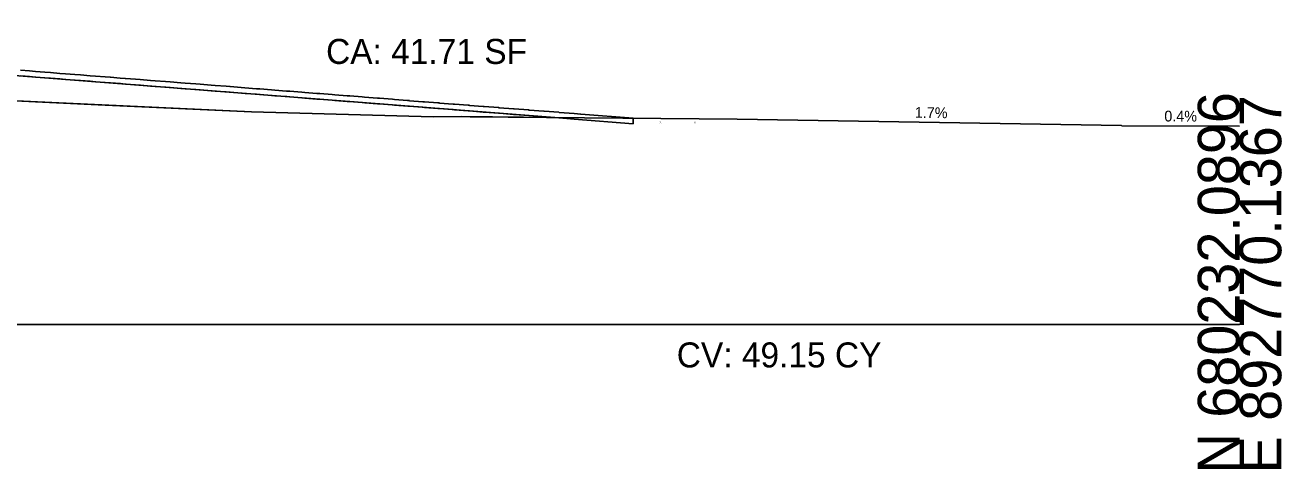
# Model space of a CAD drawing. Extents: x -26 to 4303, y -13 to 10775.
# Drawn here: x 218.5 to 302.8, y 1490.3 to 1520.1 of the extents above; entities that cross this region are included whole.
import ezdxf

# ---------------------------------------------------------------- set-up
doc = ezdxf.new("R2010")
doc.units = 0
for name, color, linetype in [('DTM_P_FINISHED_GRADE', 7, 'Continuous'), ('DTM_X_GROUND', 7, 'Continuous'), ('X_PROFILES_1', 7, 'Continuous'), ('XS_CELL', 7, 'Continuous'), ('XS_M_SHAPES_EARTHWORK', 7, 'Continuous'), ('XS_P_DR_GRAVEL', 7, 'Continuous'), ('XS_P_TX_FS_BS', 7, 'Continuous'), ('XS_SHEET_EW_TX_AREA', 7, 'Continuous'), ('XS_SHEET_EW_TX_VOLUME', 7, 'Continuous')]:
    doc.layers.add(name, color=color, linetype=linetype)

msp = doc.modelspace()

# ---------------------------------------------------------------- linework, layer by layer
at = {"layer": 'DTM_P_FINISHED_GRADE'}
for p, q in [((218.212, 1517.075), (218.812, 1517.028)), ((218.812, 1517.028), (219.21, 1516.997)), ((219.21, 1516.997), (219.216, 1516.997)), ((219.216, 1516.997), (219.826, 1516.949)), ((219.826, 1516.949), (220.214, 1516.919)), ((220.214, 1516.919), (220.22, 1516.918)), ((220.22, 1516.918), (220.841, 1516.869)), ((220.841, 1516.869), (221.218, 1516.84)), ((221.218, 1516.84), (221.223, 1516.84)), ((221.223, 1516.84), (221.856, 1516.79)), ((221.856, 1516.79), (222.221, 1516.762)), ((222.221, 1516.762), (222.227, 1516.761)), ((222.227, 1516.761), (222.871, 1516.711)), ((222.871, 1516.711), (223.225, 1516.683)), ((223.225, 1516.683), (223.231, 1516.683)), ((223.231, 1516.683), (223.885, 1516.631)), ((223.885, 1516.631), (224.229, 1516.605)), ((224.229, 1516.605), (224.234, 1516.604)), ((224.234, 1516.604), (224.9, 1516.552)), ((224.9, 1516.552), (225.233, 1516.526)), ((225.233, 1516.526), (225.238, 1516.526)), ((225.238, 1516.526), (225.915, 1516.473)), ((225.915, 1516.473), (226.237, 1516.448)), ((226.237, 1516.448), (226.242, 1516.447)), ((226.242, 1516.447), (226.93, 1516.393)), ((226.93, 1516.393), (227.24, 1516.369)), ((227.24, 1516.369), (227.245, 1516.369)), ((227.245, 1516.369), (227.944, 1516.314)), ((227.944, 1516.314), (228.244, 1516.291)), ((228.244, 1516.291), (228.249, 1516.29)), ((228.249, 1516.29), (228.959, 1516.235)), ((228.959, 1516.235), (229.248, 1516.212)), ((229.248, 1516.212), (229.252, 1516.212)), ((229.252, 1516.212), (229.974, 1516.155)), ((229.974, 1516.155), (230.252, 1516.134)), ((230.252, 1516.134), (230.256, 1516.133)), ((230.256, 1516.133), (230.989, 1516.076)), ((230.989, 1516.076), (231.256, 1516.055)), ((231.256, 1516.055), (231.26, 1516.055)), ((231.26, 1516.055), (232.003, 1515.997)), ((232.003, 1515.997), (232.26, 1515.977)), ((232.26, 1515.977), (232.263, 1515.976)), ((232.263, 1515.976), (233.018, 1515.917)), ((233.018, 1515.917), (233.263, 1515.898)), ((233.263, 1515.898), (233.267, 1515.898)), ((233.267, 1515.898), (234.033, 1515.838)), ((234.033, 1515.838), (234.267, 1515.82)), ((234.267, 1515.82), (234.271, 1515.819)), ((234.271, 1515.819), (235.048, 1515.758)), ((235.048, 1515.758), (235.271, 1515.741)), ((235.271, 1515.741), (235.274, 1515.741)), ((235.274, 1515.741), (236.062, 1515.679)), ((236.062, 1515.679), (236.275, 1515.663)), ((236.275, 1515.663), (236.278, 1515.662)), ((236.278, 1515.662), (237.077, 1515.6)), ((237.077, 1515.6), (237.279, 1515.584)), ((237.279, 1515.584), (237.282, 1515.584)), ((237.282, 1515.584), (238.092, 1515.52)), ((238.092, 1515.52), (238.282, 1515.506)), ((238.282, 1515.506), (238.285, 1515.505)), ((238.285, 1515.505), (239.106, 1515.441)), ((239.106, 1515.441), (239.286, 1515.427)), ((239.286, 1515.427), (239.289, 1515.427)), ((239.289, 1515.427), (240.121, 1515.362)), ((240.121, 1515.362), (240.29, 1515.349)), ((240.29, 1515.349), (240.293, 1515.348)), ((240.293, 1515.348), (241.136, 1515.282)), ((241.136, 1515.282), (241.294, 1515.27)), ((241.294, 1515.27), (241.296, 1515.27)), ((241.296, 1515.27), (242.151, 1515.203)), ((242.151, 1515.203), (242.298, 1515.192)), ((242.298, 1515.192), (242.3, 1515.191)), ((242.3, 1515.191), (243.166, 1515.124)), ((243.166, 1515.124), (243.302, 1515.113)), ((243.302, 1515.113), (243.304, 1515.113)), ((243.304, 1515.113), (244.18, 1515.044)), ((244.18, 1515.044), (244.305, 1515.035)), ((244.305, 1515.035), (244.307, 1515.034)), ((244.307, 1515.034), (245.195, 1514.965)), ((245.195, 1514.965), (245.309, 1514.956)), ((245.309, 1514.956), (245.311, 1514.956)), ((245.311, 1514.956), (246.21, 1514.886)), ((246.21, 1514.886), (246.313, 1514.878)), ((246.313, 1514.878), (246.315, 1514.877)), ((246.315, 1514.877), (247.225, 1514.806)), ((247.225, 1514.806), (247.317, 1514.799)), ((247.317, 1514.799), (247.318, 1514.799)), ((247.318, 1514.799), (248.239, 1514.727)), ((248.239, 1514.727), (248.321, 1514.721)), ((248.321, 1514.721), (248.322, 1514.72)), ((248.322, 1514.72), (249.254, 1514.648)), ((249.254, 1514.648), (249.324, 1514.642)), ((249.324, 1514.642), (249.325, 1514.642)), ((249.325, 1514.642), (250.269, 1514.568)), ((250.269, 1514.568), (250.328, 1514.564)), ((250.328, 1514.564), (250.329, 1514.563)), ((250.329, 1514.563), (251.284, 1514.489)), ((251.284, 1514.489), (251.332, 1514.485)), ((251.332, 1514.485), (251.333, 1514.485)), ((251.333, 1514.485), (252.298, 1514.409)), ((252.298, 1514.409), (252.336, 1514.407)), ((252.336, 1514.407), (252.337, 1514.406)), ((252.337, 1514.406), (253.313, 1514.33)), ((253.313, 1514.33), (253.34, 1514.328)), ((253.34, 1514.328), (253.34, 1514.328)), ((253.34, 1514.328), (254.328, 1514.251)), ((254.328, 1514.251), (254.343, 1514.25)), ((254.343, 1514.25), (254.344, 1514.25)), ((254.344, 1514.25), (255.343, 1514.171)), ((255.343, 1514.171), (255.347, 1514.171)), ((255.347, 1514.171), (255.347, 1514.171)), ((255.347, 1514.171), (255.789, 1514.136))]:
    msp.add_line(p, q, dxfattribs=at)
at = {"layer": 'DTM_X_GROUND'}
msp.add_lwpolyline([(214.069, 1515.192), (233.709, 1514.282), (245.883, 1513.954), (247.772, 1513.966), (248.38, 1513.947), (266.299, 1513.788), (292.07, 1513.357), (292.103, 1513.35), (300, 1513.32)], dxfattribs=at)
at = {"layer": 'XS_CELL'}
msp.add_line((150, 1500), (300, 1500), dxfattribs=at)
at = {"layer": 'XS_P_DR_GRAVEL'}
for p, q in [((218.812, 1517.028), (218.212, 1517.075)), ((219.21, 1516.997), (218.812, 1517.028)), ((218.218, 1516.7), (218.817, 1516.653)), ((218.817, 1516.653), (219.215, 1516.622)), ((219.216, 1516.997), (219.21, 1516.997)), ((219.215, 1516.622), (219.221, 1516.621)), ((219.826, 1516.949), (219.216, 1516.997)), ((219.221, 1516.621), (219.832, 1516.574)), ((220.214, 1516.919), (219.826, 1516.949)), ((219.832, 1516.574), (220.219, 1516.543)), ((220.22, 1516.918), (220.214, 1516.919)), ((220.219, 1516.543), (220.225, 1516.543)), ((220.841, 1516.869), (220.22, 1516.918)), ((220.225, 1516.543), (220.847, 1516.494)), ((221.218, 1516.84), (220.841, 1516.869)), ((220.847, 1516.494), (221.223, 1516.465)), ((221.223, 1516.84), (221.218, 1516.84)), ((221.856, 1516.79), (221.223, 1516.84)), ((221.223, 1516.465), (221.229, 1516.464)), ((221.229, 1516.464), (221.861, 1516.415)), ((222.221, 1516.762), (221.856, 1516.79)), ((221.861, 1516.415), (222.227, 1516.386)), ((222.227, 1516.761), (222.221, 1516.762)), ((222.871, 1516.711), (222.227, 1516.761)), ((222.227, 1516.386), (222.232, 1516.386)), ((222.232, 1516.386), (222.876, 1516.336)), ((223.225, 1516.683), (222.871, 1516.711)), ((222.876, 1516.336), (223.231, 1516.308)), ((223.231, 1516.683), (223.225, 1516.683)), ((223.885, 1516.631), (223.231, 1516.683)), ((223.231, 1516.308), (223.236, 1516.307)), ((223.236, 1516.307), (223.891, 1516.256)), ((224.229, 1516.605), (223.885, 1516.631)), ((223.891, 1516.256), (224.234, 1516.229)), ((224.234, 1516.604), (224.229, 1516.605)), ((224.9, 1516.552), (224.234, 1516.604)), ((224.234, 1516.229), (224.24, 1516.229)), ((224.24, 1516.229), (224.906, 1516.177)), ((225.233, 1516.526), (224.9, 1516.552)), ((224.906, 1516.177), (225.238, 1516.151)), ((225.238, 1516.526), (225.233, 1516.526)), ((225.915, 1516.473), (225.238, 1516.526)), ((226.237, 1516.448), (225.915, 1516.473)), ((226.242, 1516.447), (226.237, 1516.448)), ((226.93, 1516.393), (226.242, 1516.447)), ((227.24, 1516.369), (226.93, 1516.393)), ((227.245, 1516.369), (227.24, 1516.369)), ((227.944, 1516.314), (227.245, 1516.369)), ((228.244, 1516.291), (227.944, 1516.314)), ((228.249, 1516.29), (228.244, 1516.291)), ((228.959, 1516.235), (228.249, 1516.29)), ((229.248, 1516.212), (228.959, 1516.235)), ((229.252, 1516.212), (229.248, 1516.212)), ((229.974, 1516.155), (229.252, 1516.212)), ((225.238, 1516.151), (225.243, 1516.15)), ((225.243, 1516.15), (225.92, 1516.098)), ((225.92, 1516.098), (226.242, 1516.072)), ((226.242, 1516.072), (226.247, 1516.072)), ((226.247, 1516.072), (226.935, 1516.018)), ((226.935, 1516.018), (227.246, 1515.994)), ((227.246, 1515.994), (227.251, 1515.994)), ((227.251, 1515.994), (227.95, 1515.939)), ((227.95, 1515.939), (228.25, 1515.915)), ((228.25, 1515.915), (228.254, 1515.915)), ((228.254, 1515.915), (228.964, 1515.859)), ((228.964, 1515.859), (229.253, 1515.837)), ((229.253, 1515.837), (229.258, 1515.837)), ((229.258, 1515.837), (229.979, 1515.78)), ((230.252, 1516.134), (229.974, 1516.155)), ((229.979, 1515.78), (230.257, 1515.758)), ((230.256, 1516.133), (230.252, 1516.134)), ((230.989, 1516.076), (230.256, 1516.133)), ((230.257, 1515.758), (230.262, 1515.758)), ((230.262, 1515.758), (230.994, 1515.701)), ((231.256, 1516.055), (230.989, 1516.076)), ((230.994, 1515.701), (231.261, 1515.68)), ((231.26, 1516.055), (231.256, 1516.055)), ((232.003, 1515.997), (231.26, 1516.055)), ((231.261, 1515.68), (231.265, 1515.68)), ((231.265, 1515.68), (232.009, 1515.621)), ((232.26, 1515.977), (232.003, 1515.997)), ((232.009, 1515.621), (232.265, 1515.601)), ((232.263, 1515.976), (232.26, 1515.977)), ((233.018, 1515.917), (232.263, 1515.976)), ((232.265, 1515.601), (232.269, 1515.601)), ((232.269, 1515.601), (233.024, 1515.542)), ((233.263, 1515.898), (233.018, 1515.917)), ((233.024, 1515.542), (233.269, 1515.523)), ((233.267, 1515.898), (233.263, 1515.898)), ((234.033, 1515.838), (233.267, 1515.898)), ((233.269, 1515.523), (233.273, 1515.523)), ((233.273, 1515.523), (234.038, 1515.463)), ((234.267, 1515.82), (234.033, 1515.838)), ((234.038, 1515.463), (234.272, 1515.444)), ((234.271, 1515.819), (234.267, 1515.82)), ((235.048, 1515.758), (234.271, 1515.819)), ((234.272, 1515.444), (234.276, 1515.444)), ((234.276, 1515.444), (235.053, 1515.383)), ((235.271, 1515.741), (235.048, 1515.758)), ((235.053, 1515.383), (235.276, 1515.366)), ((235.274, 1515.741), (235.271, 1515.741)), ((236.062, 1515.679), (235.274, 1515.741)), ((235.276, 1515.366), (235.28, 1515.366)), ((235.28, 1515.366), (236.068, 1515.304)), ((236.275, 1515.663), (236.062, 1515.679)), ((236.278, 1515.662), (236.275, 1515.663)), ((237.077, 1515.6), (236.278, 1515.662)), ((237.279, 1515.584), (237.077, 1515.6)), ((237.282, 1515.584), (237.279, 1515.584)), ((238.092, 1515.52), (237.282, 1515.584)), ((238.282, 1515.506), (238.092, 1515.52)), ((238.285, 1515.505), (238.282, 1515.506)), ((239.106, 1515.441), (238.285, 1515.505)), ((239.286, 1515.427), (239.106, 1515.441)), ((239.289, 1515.427), (239.286, 1515.427)), ((240.121, 1515.362), (239.289, 1515.427)), ((240.29, 1515.349), (240.121, 1515.362)), ((240.293, 1515.348), (240.29, 1515.349)), ((241.136, 1515.282), (240.293, 1515.348)), ((236.068, 1515.304), (236.28, 1515.287)), ((236.28, 1515.287), (236.284, 1515.287)), ((236.284, 1515.287), (237.083, 1515.225)), ((237.083, 1515.225), (237.284, 1515.209)), ((237.284, 1515.209), (237.287, 1515.209)), ((237.287, 1515.209), (238.097, 1515.145)), ((238.097, 1515.145), (238.288, 1515.13)), ((238.288, 1515.13), (238.291, 1515.13)), ((238.291, 1515.13), (239.112, 1515.066)), ((239.112, 1515.066), (239.292, 1515.052)), ((239.292, 1515.052), (239.294, 1515.052)), ((239.294, 1515.052), (240.127, 1514.987)), ((240.127, 1514.987), (240.296, 1514.973)), ((240.296, 1514.973), (240.298, 1514.973)), ((240.298, 1514.973), (241.142, 1514.907)), ((241.294, 1515.27), (241.136, 1515.282)), ((241.142, 1514.907), (241.299, 1514.895)), ((241.296, 1515.27), (241.294, 1515.27)), ((242.151, 1515.203), (241.296, 1515.27)), ((241.299, 1514.895), (241.302, 1514.895)), ((241.302, 1514.895), (242.156, 1514.828)), ((242.298, 1515.192), (242.151, 1515.203)), ((242.156, 1514.828), (242.303, 1514.816)), ((242.3, 1515.191), (242.298, 1515.192)), ((243.166, 1515.124), (242.3, 1515.191)), ((242.303, 1514.816), (242.305, 1514.816)), ((242.305, 1514.816), (243.171, 1514.749)), ((243.302, 1515.113), (243.166, 1515.124)), ((243.171, 1514.749), (243.307, 1514.738)), ((243.304, 1515.113), (243.302, 1515.113)), ((244.18, 1515.044), (243.304, 1515.113)), ((243.307, 1514.738), (243.309, 1514.738)), ((243.309, 1514.738), (244.186, 1514.669)), ((244.305, 1515.035), (244.18, 1515.044)), ((244.186, 1514.669), (244.311, 1514.659)), ((244.307, 1515.034), (244.305, 1515.035)), ((245.195, 1514.965), (244.307, 1515.034)), ((244.311, 1514.659), (244.313, 1514.659)), ((244.313, 1514.659), (245.201, 1514.59)), ((245.309, 1514.956), (245.195, 1514.965)), ((245.201, 1514.59), (245.315, 1514.581)), ((245.311, 1514.956), (245.309, 1514.956)), ((246.21, 1514.886), (245.311, 1514.956)), ((245.315, 1514.581), (245.316, 1514.581)), ((245.316, 1514.581), (246.215, 1514.51)), ((246.313, 1514.878), (246.21, 1514.886)), ((246.215, 1514.51), (246.318, 1514.502)), ((246.315, 1514.877), (246.313, 1514.878)), ((247.225, 1514.806), (246.315, 1514.877)), ((246.318, 1514.502), (246.32, 1514.502)), ((246.32, 1514.502), (247.23, 1514.431)), ((247.317, 1514.799), (247.225, 1514.806)), ((247.318, 1514.799), (247.317, 1514.799)), ((248.239, 1514.727), (247.318, 1514.799)), ((248.321, 1514.721), (248.239, 1514.727)), ((248.322, 1514.72), (248.321, 1514.721)), ((249.254, 1514.648), (248.322, 1514.72)), ((249.324, 1514.642), (249.254, 1514.648)), ((249.325, 1514.642), (249.324, 1514.642)), ((250.269, 1514.568), (249.325, 1514.642)), ((250.328, 1514.564), (250.269, 1514.568)), ((250.329, 1514.563), (250.328, 1514.564)), ((251.284, 1514.489), (250.329, 1514.563)), ((251.332, 1514.485), (251.284, 1514.489)), ((251.333, 1514.485), (251.332, 1514.485)), ((252.298, 1514.409), (251.333, 1514.485)), ((247.23, 1514.431), (247.322, 1514.424)), ((247.322, 1514.424), (247.324, 1514.424)), ((247.324, 1514.424), (248.245, 1514.352)), ((248.245, 1514.352), (248.326, 1514.345)), ((248.326, 1514.345), (248.327, 1514.345)), ((248.327, 1514.345), (249.259, 1514.272)), ((249.259, 1514.272), (249.33, 1514.267)), ((249.33, 1514.267), (249.331, 1514.267)), ((249.331, 1514.267), (250.274, 1514.193)), ((250.274, 1514.193), (250.334, 1514.188)), ((250.334, 1514.188), (250.335, 1514.188)), ((250.335, 1514.188), (251.289, 1514.114)), ((251.289, 1514.114), (251.338, 1514.11)), ((251.338, 1514.11), (251.338, 1514.11)), ((251.338, 1514.11), (252.304, 1514.034)), ((252.336, 1514.407), (252.298, 1514.409)), ((252.304, 1514.034), (252.341, 1514.031)), ((252.337, 1514.406), (252.336, 1514.407)), ((253.313, 1514.33), (252.337, 1514.406)), ((252.341, 1514.031), (252.342, 1514.031)), ((252.342, 1514.031), (253.319, 1513.955)), ((253.34, 1514.328), (253.313, 1514.33)), ((253.319, 1513.955), (253.345, 1513.953)), ((254.328, 1514.251), (253.34, 1514.328)), ((253.34, 1514.328), (253.34, 1514.328)), ((253.345, 1513.953), (253.346, 1513.953)), ((253.346, 1513.953), (254.333, 1513.876)), ((254.343, 1514.25), (254.328, 1514.251)), ((254.333, 1513.876), (254.349, 1513.874)), ((254.344, 1514.25), (254.343, 1514.25)), ((255.343, 1514.171), (254.344, 1514.25)), ((254.349, 1513.874), (254.349, 1513.874)), ((254.349, 1513.874), (255.348, 1513.796)), ((255.347, 1514.171), (255.343, 1514.171)), ((255.795, 1514.136), (255.347, 1514.171)), ((255.347, 1514.171), (255.347, 1514.171)), ((255.348, 1513.796), (255.353, 1513.796)), ((255.353, 1513.796), (255.353, 1513.796)), ((255.353, 1513.796), (259.306, 1513.487)), ((255.795, 1514.136), (259.306, 1513.85)), ((259.306, 1513.487), (259.306, 1513.85))]:
    msp.add_line(p, q, dxfattribs=at)
at = {"layer": 'XS_SHEET_EW_TX_AREA'}
msp.add_lwpolyline([(170.525, 1520.108), (174.873, 1519), (177.053, 1518.46), (179.846, 1518.137), (186.838, 1517.423), (193.83, 1516.708), (200.127, 1516.171), (203.804, 1515.876), (209.501, 1515.398), (214.069, 1515.192), (223.889, 1514.737), (233.709, 1514.282), (245.883, 1513.954), (247.772, 1513.966), (254.06, 1513.902), (235.674, 1515.335), (221.545, 1516.44), (209.185, 1517.406), (195.478, 1518.478), (186.719, 1519.163), (179.654, 1519.701)], close=True, dxfattribs=at)

# ---------------------------------------------------------------- texts
at = {"layer": 'X_PROFILES_1'}
for p in [(261.089, 1513.522), (263.406, 1513.502)]:
    msp.add_text('X', height=0.12, dxfattribs=at).set_placement(p)
at = {"layer": 'XS_CELL'}
for s, p in [('N 680232.0896', (300, 1490)), ('E 892770.1367', (302.8, 1490))]:
    msp.add_text(s, height=2.8, rotation=90, dxfattribs=at).set_placement(p)
at = {"layer": 'XS_M_SHAPES_EARTHWORK'}
msp.add_text('CV: 49.15 CY', height=1.68, dxfattribs=at).set_placement((262.237, 1497.12))
at = {"layer": 'XS_P_TX_FS_BS'}
for s, rotation, p in [('1.7%', 359.04106, (278.207, 1513.889)), ('0.4%', 359.78257, (294.951, 1513.639))]:
    msp.add_text(s, height=0.72, rotation=rotation, dxfattribs=at).set_placement(p)
at = {"layer": 'XS_SHEET_EW_TX_VOLUME'}
msp.add_text('CA: 41.71 SF', height=1.68, dxfattribs=at).set_placement((238.707, 1517.5))

doc.saveas('drawing.dxf')
